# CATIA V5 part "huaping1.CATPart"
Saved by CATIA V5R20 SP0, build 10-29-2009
Part number: 花瓶
Material "Wallpaper Strip 2": density 2120 kg/m3, Young's modulus 2.56e+10 Pa, Poisson ratio 0.22
Material "Bathroom Floor": density 2770 kg/m3, Young's modulus 6e+10 Pa, Poisson ratio 0.3
Bounding box of the stored display mesh (mm): x -41.18 to 41.18, y -41.197 to 41.155, z 0 to 145.319
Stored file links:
  C:\Users\Lenovo\Desktop\huaping1.CATPart
  F:\catia\win_b64\startup\materials\Catalog.CATMaterial
  F:\catia\win_b64\startup\materials\blue_env_512x512.jpg
  F:\catia\win_b64\startup\materials\lead.jpg
  F:\catia\win_b64\startup\materials\eroded_metal_1.jpg
  F:\catia\win_b64\startup\materials\brushed_metal2.jpg
  F:\catia\win_b64\startup\materials\blue_fabric_02.jpg
  F:\catia\win_b64\startup\materials\black_leather.jpg
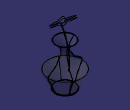
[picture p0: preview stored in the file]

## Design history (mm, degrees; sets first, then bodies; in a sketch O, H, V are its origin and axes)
Body1 (main body), material "Bathroom Floor"
  Plane1: linked copy from another document
  Plane2: type Offset, RefPlane xy-plane, Offset 20
  Plane3: type Offset, RefPlane Plane2, Offset 20
  Plane4: type Offset, RefPlane Plane3, Offset 20
  Plane5: type Offset, RefPlane Plane4, Offset 20
  Plane6: type Offset, RefPlane Plane5, Offset 20
  Sketch1 on Plane1, origin (0, 0, 0), H (1, 0, 0), V (0, 1, 0)
    circle A1 centre (0, 0) radius 20
  Sketch2 on Plane5, origin (0, 0, 80), H (1, 0, 0), V (0, 1, 0)
  Sketch3 on Plane4, origin (0, 0, 60), H (1, 0, 0), V (0, 1, 0)
  Sketch4 on Plane2, origin (0, 0, 20), H (1, 0, 0), V (0, 1, 0)
  Sketch5 on Plane5, origin (0, 0, 80), H (1, 0, 0), V (0, 1, 0)
  Sketch6 on Plane6, origin (0, 0, 100), H (1, 0, 0), V (0, 1, 0)
    circle A1 centre (0, 0) radius 22.3607
  Sketch7 on Plane5, origin (0, 0, 80), H (1, 0, 0), V (0, 1, 0)
    point P1 (90, 0)
    circle A1 centre (0, 0) radius 10
    coincidence: P1 H
  Sketch8 on Plane4, origin (0, 0, 60), H (1, 0, 0), V (0, 1, 0)
    circle A1 centre (0, 0) radius 20
  Sketch9 on Plane3, origin (0, 0, 40), H (1, 0, 0), V (0, 1, 0)
    circle A1 centre (0, 0) radius 41.2311
  Sketch10 on Plane2, origin (0, 0, 20), H (1, 0, 0), V (0, 1, 0)
    circle A1 centre (0, 0) radius 31.6228
    construction line L1 through (0, 0) direction (1, 0)
  Sketch11 on Plane1, origin (0, 0, 0), H (1, 0, 0), V (0, 1, 0)
    circle A1 centre (0, 0) radius 23.5
  Loft1: solid, Sections (Sketch6; Sketch7; Sketch8; Sketch9; Sketch10; Sketch11)
  Shell1: IntOffset 1, ExtOffset 0
  Shell2: IntOffset 1, Face face of Loft1, ExtOffset 0
Body2
  Sketch12 on yz-plane, origin (0, 0, 0), H (0, 1, 0), V (0, 0, 1)
    axis line L1 (0, 109.9957) -> (0, -8.9151)
    point P1 (0, 109.9957)
    point P3 (0, 39.8688)
    line L2 (0, 39.8688) -> (39.4903, 39.8688)
    line L3 (39.4903, 39.8688) -> (22.5305, 1.8949)
    line L4 (22.5305, 1.8949) -> (0, 1.8949)
    point P6 (0, 1.8949)
    coincidence: P1 V, P3 L1, P6 L1
    vertical: L1 V
    horizontal: L2 H, L4 H
  Shaft1: profile Sketch12, axis Sketch12.L1, angle 360
  Sketch13 on yz-plane, origin (0, 0, 0), H (0, 1, 0), V (0, 0, 1)
    spline S1 through (0, 10) (10, 50) (-10, 130)
    point P1 (0, 10)
    coincidence: P1 V
  Plane7: type Normal, Curve Sketch13, RefPoint vertex of Sketch13
  Sketch14 on Plane7, origin (0, -59.1192, 101.3472), H (1, 0, 0), V (0, 0.8638, 0.5039)
    spline S1 through (0, 70) (10, 80) (10, 60)
    spline S2 through (10, 60) (20, 50) (0, 50)
    spline S3 through (0, 50) (-20, 40) (-10, 60)
    spline S4 through (0, 70) (-20, 80) (-10, 60)
    point P1 (0, 70)
    point P2 (10, 60)
    point P3 (10, 60)
    point P4 (0, 50)
    point P5 (0, 50)
    point P6 (-10, 60)
    point P7 (0, 70)
    point P8 (-10, 60)
    coincidence: P1 V, P3 P2, P5 P4, P7 P1, P8 P6
  Circle1: type CtrRad, Start 0, End 180, Radius 1, Center vertex of Sketch13, Support Plane7, FirstDirection (1, 0, 0)
  Rib1: profile Circle1, centre curve Sketch13
  Pad1: profile Sketch14, direction (0, -0.5039, 0.8638), length 4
